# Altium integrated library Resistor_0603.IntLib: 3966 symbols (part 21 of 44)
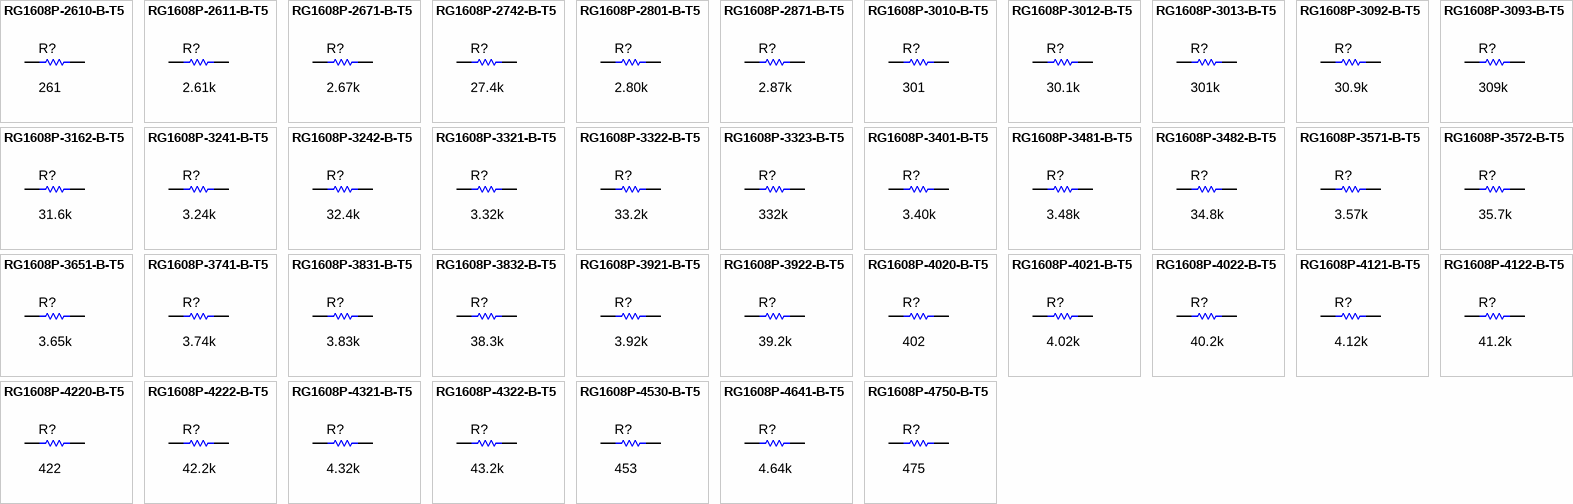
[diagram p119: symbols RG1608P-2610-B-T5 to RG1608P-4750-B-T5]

## RG1608P-2871-B-T5
designator R?  ValueDisplayed: 2.87k  (hidden comment: RG1608P-2871-B-T5)
RES, 2.87 k, 0.1%, 0.1 W, 0603; Manufacturer: Susumu Co Ltd; CompType: Resistor; Value: 2.87k; Res_ohm: 2870; Value_Code: 2k87; Tolerance_%: 0.1; Value2: 0.1W; VDC_V: 75; TempCo: 25 ppm/C; SizeArea_mm2: 1.28; SizeX_mm: 1.6; SizeY_mm: 0.8; SizeZ_mm: 1; EIA_Code: E192; U/M: EA; AEC Category: Q200; Green_Lifecycle: Active; Green_REACh: Passed
signal-integrity model Resistor
simulation model Resistor
footprint 0603
footprint 0603M
footprint 0603L
footprint 0603_HV
footprint 0603S
pins: 1, 2

## RG1608P-3010-B-T5
designator R?  ValueDisplayed: 301  (hidden comment: RG1608P-3010-B-T5)
RES, 301, 0.1%, 0.1 W, 0603; Manufacturer: Susumu Co Ltd; CompType: Resistor; Value: 301; Value_Code: 301R; Tolerance_%: 0.1; Value2: 0.1W; VDC_V: 75; TempCo: 25 ppm/C; SizeArea_mm2: 1.28; SizeX_mm: 1.6; SizeY_mm: 0.8; SizeZ_mm: 1; EIA_Code: E192; U/M: EA; AEC Category: Q200
signal-integrity model Resistor
simulation model Resistor
footprint 0603
footprint 0603M
footprint 0603L
footprint 0603_HV
footprint 0603S
pins: 1, 2

## RG1608P-3012-B-T5
designator R?  ValueDisplayed: 30.1k  (hidden comment: RG1608P-3012-B-T5)
RES, 30.1 k, 0.1%, 0.1 W, 0603; Manufacturer: Susumu Co Ltd; CompType: Resistor; Value: 30.1k; Res_ohm: 30100; Value_Code: 30k1; Tolerance_%: 0.1; Value2: 0.1W; VDC_V: 75; TempCo: 25 ppm/C; SizeArea_mm2: 1.28; SizeX_mm: 1.6; SizeY_mm: 0.8; SizeZ_mm: 1; EIA_Code: E192; U/M: EA; AEC Category: Q200; Green_Lifecycle: Active; Green_REACh: Passed
signal-integrity model Resistor
simulation model Resistor
footprint 0603
footprint 0603M
footprint 0603L
footprint 0603_HV
footprint 0603S
pins: 1, 2

## RG1608P-3013-B-T5
designator R?  ValueDisplayed: 301k  (hidden comment: RG1608P-3013-B-T5)
RES, 301 k, 0.1%, 0.1 W, 0603; Manufacturer: Susumu Co Ltd; CompType: Resistor; Value: 301k; Res_ohm: 301000; Tolerance_%: 0.1; Value2: 0.1W; VDC_V: 75; TempCo: 25 ppm/C; SizeArea_mm2: 1.28; SizeX_mm: 1.6; SizeY_mm: 0.8; SizeZ_mm: 1; EIA_Code: E192; U/M: EA; AEC Category: Q200
signal-integrity model Resistor
simulation model Resistor
footprint 0603
footprint 0603M
footprint 0603L
footprint 0603_HV
footprint 0603S
pins: 1, 2

## RG1608P-3092-B-T5
designator R?  ValueDisplayed: 30.9k  (hidden comment: RG1608P-3092-B-T5)
RES, 30.9 k, 0.1%, 0.1 W, 0603; Manufacturer: Susumu Co Ltd; CompType: Resistor; Value: 30.9k; Res_ohm: 30900; Value_Code: 30k9; Tolerance_%: 0.1; Value2: 0.1W; VDC_V: 75; TempCo: 25 ppm/C; SizeArea_mm2: 1.28; SizeX_mm: 1.6; SizeY_mm: 0.8; SizeZ_mm: 1; EIA_Code: E192; U/M: EA; AEC Category: Q200
signal-integrity model Resistor
simulation model Resistor
footprint 0603
footprint 0603M
footprint 0603L
footprint 0603_HV
footprint 0603S
pins: 1, 2

## RG1608P-3093-B-T5
designator R?  ValueDisplayed: 309k  (hidden comment: RG1608P-3093-B-T5)
RES, 309 k, 0.1%, 0.1 W, 0603; Manufacturer: Susumu Co Ltd; CompType: Resistor; Value: 309k; Res_ohm: 309000; Tolerance_%: 0.1; Value2: 0.1W; VDC_V: 75; TempCo: 25 ppm/C; SizeArea_mm2: 1.28; SizeX_mm: 1.6; SizeY_mm: 0.8; SizeZ_mm: 1; EIA_Code: E192; U/M: EA; AEC Category: Q200
signal-integrity model Resistor
simulation model Resistor
footprint 0603
footprint 0603M
footprint 0603L
footprint 0603_HV
footprint 0603S
pins: 1, 2

## RG1608P-3162-B-T5
designator R?  ValueDisplayed: 31.6k  (hidden comment: RG1608P-3162-B-T5)
RES, 31.6 k, 0.1%, 0.1 W, 0603; Manufacturer: Susumu Co Ltd; CompType: Resistor; Value: 31.6k; Res_ohm: 31600; Value_Code: 31k6; Tolerance_%: 0.1; Value2: 0.1W; VDC_V: 75; TempCo: 25 ppm/C; SizeArea_mm2: 1.28; SizeX_mm: 1.6; SizeY_mm: 0.8; SizeZ_mm: 1; EIA_Code: E192; U/M: EA; AEC Category: Q200
signal-integrity model Resistor
simulation model Resistor
footprint 0603
footprint 0603M
footprint 0603L
footprint 0603_HV
footprint 0603S
pins: 1, 2

## RG1608P-3241-B-T5
designator R?  ValueDisplayed: 3.24k  (hidden comment: RG1608P-3241-B-T5)
RES, 3.24 k, 0.1%, 0.1 W, 0603; Manufacturer: Susumu Co Ltd; CompType: Resistor; Value: 3.24k; Res_ohm: 3240; Value_Code: 3k24; Tolerance_%: 0.1; Value2: 0.1W; VDC_V: 75; TempCo: 25 ppm/C; SizeArea_mm2: 1.28; SizeX_mm: 1.6; SizeY_mm: 0.8; SizeZ_mm: 1; EIA_Code: E192; U/M: EA; AEC Category: Q200
signal-integrity model Resistor
simulation model Resistor
footprint 0603
footprint 0603M
footprint 0603L
footprint 0603_HV
footprint 0603S
pins: 1, 2

## RG1608P-3242-B-T5
designator R?  ValueDisplayed: 32.4k  (hidden comment: RG1608P-3242-B-T5)
RES, 32.4 k, 0.1%, 0.1 W, 0603; Manufacturer: Susumu Co Ltd; CompType: Resistor; Value: 32.4k; Res_ohm: 32400; Value_Code: 32k4; Tolerance_%: 0.1; Value2: 0.1W; VDC_V: 75; TempCo: 25 ppm/C; SizeArea_mm2: 1.28; SizeX_mm: 1.6; SizeY_mm: 0.8; SizeZ_mm: 1; EIA_Code: E192; U/M: EA; AEC Category: Q200; Green_Lifecycle: Active; Green_REACh: Passed
signal-integrity model Resistor
simulation model Resistor
footprint 0603
footprint 0603M
footprint 0603L
footprint 0603_HV
footprint 0603S
pins: 1, 2

## RG1608P-3321-B-T5
designator R?  ValueDisplayed: 3.32k  (hidden comment: RG1608P-3321-B-T5)
RES, 3.32 k, 0.1%, 0.1 W, 0603; Manufacturer: Susumu Co Ltd; CompType: Resistor; Value: 3.32k; Res_ohm: 3320; Value_Code: 3k32; Tolerance_%: 0.1; Value2: 0.1W; VDC_V: 75; TempCo: 25 ppm/C; SizeArea_mm2: 1.28; SizeX_mm: 1.6; SizeY_mm: 0.8; SizeZ_mm: 1; EIA_Code: E192; U/M: EA; AEC Category: Q200
signal-integrity model Resistor
simulation model Resistor
footprint 0603
footprint 0603M
footprint 0603L
footprint 0603_HV
footprint 0603S
pins: 1, 2

## RG1608P-3322-B-T5
designator R?  ValueDisplayed: 33.2k  (hidden comment: RG1608P-3322-B-T5)
RES, 33.2 k, 0.1%, 0.1 W, 0603; Manufacturer: Susumu Co Ltd; CompType: Resistor; Value: 33.2k; Res_ohm: 33200; Value_Code: 33k2; Tolerance_%: 0.1; Value2: 0.1W; VDC_V: 75; TempCo: 25 ppm/C; SizeArea_mm2: 1.28; SizeX_mm: 1.6; SizeY_mm: 0.8; SizeZ_mm: 1; EIA_Code: E192; U/M: EA; AEC Category: Q200
signal-integrity model Resistor
simulation model Resistor
footprint 0603
footprint 0603M
footprint 0603L
footprint 0603_HV
footprint 0603S
pins: 1, 2

## RG1608P-3323-B-T5
designator R?  ValueDisplayed: 332k  (hidden comment: RG1608P-3323-B-T5)
RES, 332 k, 0.1%, 0.1 W, 0603; Manufacturer: Susumu Co Ltd; CompType: Resistor; Value: 332k; Res_ohm: 332000; Tolerance_%: 0.1; Value2: 0.1W; VDC_V: 75; TempCo: 25 ppm/C; SizeArea_mm2: 1.28; SizeX_mm: 1.6; SizeY_mm: 0.8; SizeZ_mm: 1; EIA_Code: E192; U/M: EA; AEC Category: Q200
signal-integrity model Resistor
simulation model Resistor
footprint 0603
footprint 0603M
footprint 0603L
footprint 0603_HV
footprint 0603S
pins: 1, 2

## RG1608P-3401-B-T5
designator R?  ValueDisplayed: 3.40k  (hidden comment: RG1608P-3401-B-T5)
RES, 3.40 k, 0.1%, 0.1 W, 0603; Manufacturer: Susumu Co Ltd; CompType: Resistor; Value: 3.40k; Res_ohm: 3400; Value_Code: 3k40; Tolerance_%: 0.1; Value2: 0.1W; VDC_V: 75; TempCo: 25 ppm/C; SizeArea_mm2: 1.28; SizeX_mm: 1.6; SizeY_mm: 0.8; SizeZ_mm: 1; EIA_Code: E192; U/M: EA; AEC Category: Q200
signal-integrity model Resistor
simulation model Resistor
footprint 0603
footprint 0603M
footprint 0603L
footprint 0603_HV
footprint 0603S
pins: 1, 2

## RG1608P-3481-B-T5
designator R?  ValueDisplayed: 3.48k  (hidden comment: RG1608P-3481-B-T5)
RES, 3.48 k, 0.1%, 0.1 W, 0603; Manufacturer: Susumu Co Ltd; CompType: Resistor; Value: 3.48k; Res_ohm: 3480; Value_Code: 3k48; Tolerance_%: 0.1; Value2: 0.1W; VDC_V: 75; TempCo: 25 ppm/C; SizeArea_mm2: 1.28; SizeX_mm: 1.6; SizeY_mm: 0.8; SizeZ_mm: 1; EIA_Code: E192; U/M: EA; AEC Category: Q200
signal-integrity model Resistor
simulation model Resistor
footprint 0603
footprint 0603M
footprint 0603L
footprint 0603_HV
footprint 0603S
pins: 1, 2

## RG1608P-3482-B-T5
designator R?  ValueDisplayed: 34.8k  (hidden comment: RG1608P-3482-B-T5)
RES, 34.8 k, 0.1%, 0.1 W, 0603; Manufacturer: Susumu Co Ltd; CompType: Resistor; Value: 34.8k; Res_ohm: 34800; Value_Code: 34k8; Tolerance_%: 0.1; Value2: 0.1W; VDC_V: 75; TempCo: 25 ppm/C; SizeArea_mm2: 1.28; SizeX_mm: 1.6; SizeY_mm: 0.8; SizeZ_mm: 1; EIA_Code: E192; U/M: EA; AEC Category: Q200
signal-integrity model Resistor
simulation model Resistor
footprint 0603
footprint 0603M
footprint 0603L
footprint 0603_HV
footprint 0603S
pins: 1, 2

## RG1608P-3571-B-T5
designator R?  ValueDisplayed: 3.57k  (hidden comment: RG1608P-3571-B-T5)
RES, 3.57 k, 0.1%, 0.1 W, 0603; Manufacturer: Susumu Co Ltd; CompType: Resistor; Value: 3.57k; Res_ohm: 3570; Value_Code: 3k57; Tolerance_%: 0.1; Value2: 0.1W; VDC_V: 75; TempCo: 25 ppm/C; SizeArea_mm2: 1.28; SizeX_mm: 1.6; SizeY_mm: 0.8; SizeZ_mm: 1; EIA_Code: E192; U/M: EA; AEC Category: Q200; Green_Lifecycle: Active; Green_REACh: Passed
signal-integrity model Resistor
simulation model Resistor
footprint 0603
footprint 0603M
footprint 0603L
footprint 0603_HV
footprint 0603S
pins: 1, 2

## RG1608P-3572-B-T5
designator R?  ValueDisplayed: 35.7k  (hidden comment: RG1608P-3572-B-T5)
RES, 35.7 k, 0.1%, 0.1 W, 0603; Manufacturer: Susumu Co Ltd; CompType: Resistor; Value: 35.7k; Res_ohm: 35700; Value_Code: 35k7; Tolerance_%: 0.1; Value2: 0.1W; VDC_V: 75; TempCo: 25 ppm/C; SizeArea_mm2: 1.28; SizeX_mm: 1.6; SizeY_mm: 0.8; SizeZ_mm: 1; EIA_Code: E192; U/M: EA; AEC Category: Q200
signal-integrity model Resistor
simulation model Resistor
footprint 0603
footprint 0603M
footprint 0603L
footprint 0603_HV
footprint 0603S
pins: 1, 2

## RG1608P-3651-B-T5
designator R?  ValueDisplayed: 3.65k  (hidden comment: RG1608P-3651-B-T5)
RES, 3.65 k, 0.1%, 0.1 W, 0603; Manufacturer: Susumu Co Ltd; CompType: Resistor; Value: 3.65k; Res_ohm: 3650; Value_Code: 3k65; Tolerance_%: 0.1; Value2: 0.1W; VDC_V: 75; TempCo: 25 ppm/C; SizeArea_mm2: 1.28; SizeX_mm: 1.6; SizeY_mm: 0.8; SizeZ_mm: 1; EIA_Code: E192; U/M: EA; AEC Category: Q200
signal-integrity model Resistor
simulation model Resistor
footprint 0603
footprint 0603M
footprint 0603L
footprint 0603_HV
footprint 0603S
pins: 1, 2

## RG1608P-3741-B-T5
designator R?  ValueDisplayed: 3.74k  (hidden comment: RG1608P-3741-B-T5)
RES, 3.74 k, 0.1%, 0.1 W, 0603; Manufacturer: Susumu Co Ltd; CompType: Resistor; Value: 3.74k; Res_ohm: 3740; Value_Code: 3k74; Tolerance_%: 0.1; Value2: 0.1W; VDC_V: 75; TempCo: 25 ppm/C; SizeArea_mm2: 1.28; SizeX_mm: 1.6; SizeY_mm: 0.8; SizeZ_mm: 1; EIA_Code: E192; U/M: EA; AEC Category: Q200
signal-integrity model Resistor
simulation model Resistor
footprint 0603
footprint 0603M
footprint 0603L
footprint 0603_HV
footprint 0603S
pins: 1, 2

## RG1608P-3831-B-T5
designator R?  ValueDisplayed: 3.83k  (hidden comment: RG1608P-3831-B-T5)
RES, 3.83 k, 0.1%, 0.1 W, 0603; Manufacturer: Susumu Co Ltd; CompType: Resistor; Value: 3.83k; Res_ohm: 3830; Value_Code: 3k83; Tolerance_%: 0.1; Value2: 0.1W; VDC_V: 75; TempCo: 25 ppm/C; SizeArea_mm2: 1.28; SizeX_mm: 1.6; SizeY_mm: 0.8; SizeZ_mm: 1; EIA_Code: E192; U/M: EA; AEC Category: Q200; Green_Lifecycle: Active; Green_REACh: Passed
signal-integrity model Resistor
simulation model Resistor
footprint 0603
footprint 0603M
footprint 0603L
footprint 0603_HV
footprint 0603S
pins: 1, 2

## RG1608P-3832-B-T5
designator R?  ValueDisplayed: 38.3k  (hidden comment: RG1608P-3832-B-T5)
RES, 38.3 k, 0.1%, 0.1 W, 0603; Manufacturer: Susumu Co Ltd; CompType: Resistor; Value: 38.3k; Res_ohm: 38300; Value_Code: 38k3; Tolerance_%: 0.1; Value2: 0.1W; VDC_V: 75; TempCo: 25 ppm/C; SizeArea_mm2: 1.28; SizeX_mm: 1.6; SizeY_mm: 0.8; SizeZ_mm: 1; EIA_Code: E192; U/M: EA; AEC Category: Q200
signal-integrity model Resistor
simulation model Resistor
footprint 0603
footprint 0603M
footprint 0603L
footprint 0603_HV
footprint 0603S
pins: 1, 2

## RG1608P-3921-B-T5
designator R?  ValueDisplayed: 3.92k  (hidden comment: RG1608P-3921-B-T5)
RES, 3.92 k, 0.1%, 0.1 W, 0603; Manufacturer: Susumu Co Ltd; CompType: Resistor; Value: 3.92k; Res_ohm: 3920; Value_Code: 3k92; Tolerance_%: 0.1; Value2: 0.1W; VDC_V: 75; TempCo: 25 ppm/C; SizeArea_mm2: 1.28; SizeX_mm: 1.6; SizeY_mm: 0.8; SizeZ_mm: 1; EIA_Code: E192; U/M: EA; AEC Category: Q200
signal-integrity model Resistor
simulation model Resistor
footprint 0603
footprint 0603M
footprint 0603L
footprint 0603_HV
footprint 0603S
pins: 1, 2

## RG1608P-3922-B-T5
designator R?  ValueDisplayed: 39.2k  (hidden comment: RG1608P-3922-B-T5)
RES, 39.2 k, 0.1%, 0.1 W, 0603; Manufacturer: Susumu Co Ltd; CompType: Resistor; Value: 39.2k; Res_ohm: 39200; Value_Code: 39k2; Tolerance_%: 0.1; Value2: 0.1W; VDC_V: 75; TempCo: 25 ppm/C; SizeArea_mm2: 1.28; SizeX_mm: 1.6; SizeY_mm: 0.8; SizeZ_mm: 1; EIA_Code: E192; U/M: EA; AEC Category: Q200; Green_Lifecycle: Active; Green_REACh: Passed
signal-integrity model Resistor
simulation model Resistor
footprint 0603
footprint 0603M
footprint 0603L
footprint 0603_HV
footprint 0603S
pins: 1, 2

## RG1608P-4020-B-T5
designator R?  ValueDisplayed: 402  (hidden comment: RG1608P-4020-B-T5)
RES, 402, 0.1%, 0.1 W, 0603; Manufacturer: Susumu Co Ltd; CompType: Resistor; Value: 402; Value_Code: 402R; Tolerance_%: 0.1; Value2: 0.1W; VDC_V: 75; TempCo: 25 ppm/C; SizeArea_mm2: 1.28; SizeX_mm: 1.6; SizeY_mm: 0.8; SizeZ_mm: 1; EIA_Code: E192; U/M: EA; AEC Category: Q200
signal-integrity model Resistor
simulation model Resistor
footprint 0603
footprint 0603M
footprint 0603L
footprint 0603_HV
footprint 0603S
pins: 1, 2

## RG1608P-4021-B-T5
designator R?  ValueDisplayed: 4.02k  (hidden comment: RG1608P-4021-B-T5)
RES, 4.02 k, 0.1%, 0.1 W, 0603; Manufacturer: Susumu Co Ltd; CompType: Resistor; Value: 4.02k; Res_ohm: 4020; Value_Code: 4k02; Tolerance_%: 0.1; Value2: 0.1W; VDC_V: 75; TempCo: 25 ppm/C; SizeArea_mm2: 1.28; SizeX_mm: 1.6; SizeY_mm: 0.8; SizeZ_mm: 1; EIA_Code: E192; U/M: EA; AEC Category: Q200
signal-integrity model Resistor
simulation model Resistor
footprint 0603
footprint 0603M
footprint 0603L
footprint 0603_HV
footprint 0603S
pins: 1, 2

## RG1608P-4022-B-T5
designator R?  ValueDisplayed: 40.2k  (hidden comment: RG1608P-4022-B-T5)
RES, 40.2 k, 0.1%, 0.1 W, 0603; Manufacturer: Susumu Co Ltd; CompType: Resistor; Value: 40.2k; Res_ohm: 40200; Value_Code: 40k2; Tolerance_%: 0.1; Value2: 0.1W; VDC_V: 75; TempCo: 25 ppm/C; SizeArea_mm2: 1.28; SizeX_mm: 1.6; SizeY_mm: 0.8; SizeZ_mm: 1; EIA_Code: E192; U/M: EA; AEC Category: Q200
signal-integrity model Resistor
simulation model Resistor
footprint 0603
footprint 0603M
footprint 0603L
footprint 0603_HV
footprint 0603S
pins: 1, 2

## RG1608P-4121-B-T5
designator R?  ValueDisplayed: 4.12k  (hidden comment: RG1608P-4121-B-T5)
RES, 4.12 k, 0.1%, 0.1 W, 0603; Manufacturer: Susumu Co Ltd; CompType: Resistor; Value: 4.12k; Res_ohm: 4120; Value_Code: 4k12; Tolerance_%: 0.1; Value2: 0.1W; VDC_V: 75; TempCo: 25 ppm/C; SizeArea_mm2: 1.28; SizeX_mm: 1.6; SizeY_mm: 0.8; SizeZ_mm: 1; EIA_Code: E192; U/M: EA; AEC Category: Q200
signal-integrity model Resistor
simulation model Resistor
footprint 0603
footprint 0603M
footprint 0603L
footprint 0603_HV
footprint 0603S
pins: 1, 2

## RG1608P-4122-B-T5
designator R?  ValueDisplayed: 41.2k  (hidden comment: RG1608P-4122-B-T5)
RES, 41.2 k, 0.1%, 0.1 W, 0603; Manufacturer: Susumu Co Ltd; CompType: Resistor; Value: 41.2k; Res_ohm: 41200; Value_Code: 41k2; Tolerance_%: 0.1; Value2: 0.1W; VDC_V: 75; TempCo: 25 ppm/C; SizeArea_mm2: 1.28; SizeX_mm: 1.6; SizeY_mm: 0.8; SizeZ_mm: 1; EIA_Code: E192; U/M: EA; AEC Category: Q200
signal-integrity model Resistor
simulation model Resistor
footprint 0603
footprint 0603M
footprint 0603L
footprint 0603_HV
footprint 0603S
pins: 1, 2

## RG1608P-4220-B-T5
designator R?  ValueDisplayed: 422  (hidden comment: RG1608P-4220-B-T5)
RES, 422, 0.1%, 0.1 W, 0603; Manufacturer: Susumu Co Ltd; CompType: Resistor; Value: 422; Value_Code: 422R; Tolerance_%: 0.1; Value2: 0.1W; VDC_V: 75; TempCo: 25 ppm/C; SizeArea_mm2: 1.28; SizeX_mm: 1.6; SizeY_mm: 0.8; SizeZ_mm: 1; EIA_Code: E192; U/M: EA; AEC Category: Q200
signal-integrity model Resistor
simulation model Resistor
footprint 0603
footprint 0603M
footprint 0603L
footprint 0603_HV
footprint 0603S
pins: 1, 2

## RG1608P-4222-B-T5
designator R?  ValueDisplayed: 42.2k  (hidden comment: RG1608P-4222-B-T5)
RES, 42.2 k, 0.1%, 0.1 W, 0603; Manufacturer: Susumu Co Ltd; CompType: Resistor; Value: 42.2k; Res_ohm: 42200; Value_Code: 42k2; Tolerance_%: 0.1; Value2: 0.1W; VDC_V: 75; TempCo: 25 ppm/C; SizeArea_mm2: 1.28; SizeX_mm: 1.6; SizeY_mm: 0.8; SizeZ_mm: 1; EIA_Code: E192; U/M: EA; AEC Category: Q200; Green_Lifecycle: Active; Green_REACh: Passed
signal-integrity model Resistor
simulation model Resistor
footprint 0603
footprint 0603M
footprint 0603L
footprint 0603_HV
footprint 0603S
pins: 1, 2

## RG1608P-4321-B-T5
designator R?  ValueDisplayed: 4.32k  (hidden comment: RG1608P-4321-B-T5)
RES, 4.32 k, 0.1%, 0.1 W, 0603; Manufacturer: Susumu Co Ltd; CompType: Resistor; Value: 4.32k; Res_ohm: 4320; Value_Code: 4k32; Tolerance_%: 0.1; Value2: 0.1W; VDC_V: 75; TempCo: 25 ppm/C; SizeArea_mm2: 1.28; SizeX_mm: 1.6; SizeY_mm: 0.8; SizeZ_mm: 1; EIA_Code: E192; U/M: EA; AEC Category: Q200
signal-integrity model Resistor
simulation model Resistor
footprint 0603
footprint 0603M
footprint 0603L
footprint 0603_HV
footprint 0603S
pins: 1, 2

## RG1608P-4322-B-T5
designator R?  ValueDisplayed: 43.2k  (hidden comment: RG1608P-4322-B-T5)
RES, 43.2 k, 0.1%, 0.1 W, 0603; Manufacturer: Susumu Co Ltd; CompType: Resistor; Value: 43.2k; Res_ohm: 43200; Value_Code: 43k2; Tolerance_%: 0.1; Value2: 0.1W; VDC_V: 75; TempCo: 25 ppm/C; SizeArea_mm2: 1.28; SizeX_mm: 1.6; SizeY_mm: 0.8; SizeZ_mm: 1; EIA_Code: E192; U/M: EA; AEC Category: Q200
signal-integrity model Resistor
simulation model Resistor
footprint 0603
footprint 0603M
footprint 0603L
footprint 0603_HV
footprint 0603S
pins: 1, 2

## RG1608P-4530-B-T5
designator R?  ValueDisplayed: 453  (hidden comment: RG1608P-4530-B-T5)
RES, 453, 0.1%, 0.1 W, 0603; Manufacturer: Susumu Co Ltd; CompType: Resistor; Value: 453; Value_Code: 453R; Tolerance_%: 0.1; Value2: 0.1W; VDC_V: 75; TempCo: 25 ppm/C; SizeArea_mm2: 1.28; SizeX_mm: 1.6; SizeY_mm: 0.8; SizeZ_mm: 1; EIA_Code: E192; U/M: EA; AEC Category: Q200
signal-integrity model Resistor
simulation model Resistor
footprint 0603
footprint 0603M
footprint 0603L
footprint 0603_HV
footprint 0603S
pins: 1, 2

## RG1608P-4641-B-T5
designator R?  ValueDisplayed: 4.64k  (hidden comment: RG1608P-4641-B-T5)
RES, 4.64 k, 0.1%, 0.1 W, 0603; Manufacturer: Susumu Co Ltd; CompType: Resistor; Value: 4.64k; Res_ohm: 4640; Value_Code: 4k64; Tolerance_%: 0.1; Value2: 0.1W; VDC_V: 75; TempCo: 25 ppm/C; SizeArea_mm2: 1.28; SizeX_mm: 1.6; SizeY_mm: 0.8; SizeZ_mm: 1; EIA_Code: E192; U/M: EA; AEC Category: Q200
signal-integrity model Resistor
simulation model Resistor
footprint 0603
footprint 0603M
footprint 0603L
footprint 0603_HV
footprint 0603S
pins: 1, 2

## RG1608P-4750-B-T5
designator R?  ValueDisplayed: 475  (hidden comment: RG1608P-4750-B-T5)
RES, 475, 0.1%, 0.1 W, 0603; Manufacturer: Susumu Co Ltd; CompType: Resistor; Value: 475; Value_Code: 475R; Tolerance_%: 0.1; Value2: 0.1W; VDC_V: 75; TempCo: 25 ppm/C; SizeArea_mm2: 1.28; SizeX_mm: 1.6; SizeY_mm: 0.8; SizeZ_mm: 1; EIA_Code: E192; U/M: EA; AEC Category: Q200
signal-integrity model Resistor
simulation model Resistor
footprint 0603
footprint 0603M
footprint 0603L
footprint 0603_HV
footprint 0603S
pins: 1, 2

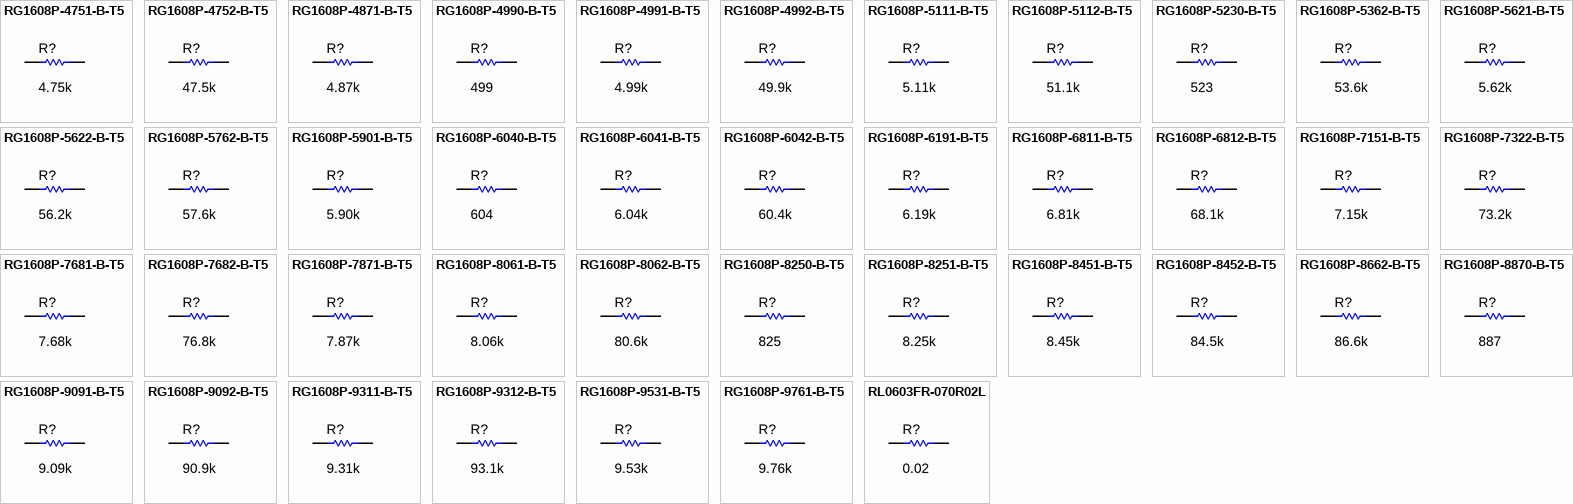
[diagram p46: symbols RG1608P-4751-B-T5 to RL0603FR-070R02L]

## RG1608P-4751-B-T5
designator R?  ValueDisplayed: 4.75k  (hidden comment: RG1608P-4751-B-T5)
RES, 4.75 k, 0.1%, 0.1 W, 0603; Manufacturer: Susumu Co Ltd; CompType: Resistor; Value: 4.75k; Res_ohm: 4750; Value_Code: 4k75; Tolerance_%: 0.1; Value2: 0.1W; VDC_V: 75; TempCo: 25 ppm/C; SizeArea_mm2: 1.28; SizeX_mm: 1.6; SizeY_mm: 0.8; SizeZ_mm: 1; EIA_Code: E192; U/M: EA; AEC Category: Q200
signal-integrity model Resistor
simulation model Resistor
footprint 0603
footprint 0603M
footprint 0603L
footprint 0603_HV
footprint 0603S
pins: 1, 2

## RG1608P-4752-B-T5
designator R?  ValueDisplayed: 47.5k  (hidden comment: RG1608P-4752-B-T5)
RES, 47.5 k, 0.1%, 0.1 W, 0603; Manufacturer: Susumu Co Ltd; CompType: Resistor; Value: 47.5k; Res_ohm: 47500; Value_Code: 47k5; Tolerance_%: 0.1; Value2: 0.1W; VDC_V: 75; TempCo: 25 ppm/C; SizeArea_mm2: 1.28; SizeX_mm: 1.6; SizeY_mm: 0.8; SizeZ_mm: 1; EIA_Code: E192; U/M: EA; AEC Category: Q200
signal-integrity model Resistor
simulation model Resistor
footprint 0603
footprint 0603M
footprint 0603L
footprint 0603_HV
footprint 0603S
pins: 1, 2

## RG1608P-4871-B-T5
designator R?  ValueDisplayed: 4.87k  (hidden comment: RG1608P-4871-B-T5)
RES, 4.87 k, 0.1%, 0.1 W, 0603; Manufacturer: Susumu Co Ltd; CompType: Resistor; Value: 4.87k; Res_ohm: 4870; Value_Code: 4k87; Tolerance_%: 0.1; Value2: 0.1W; VDC_V: 75; TempCo: 25 ppm/C; SizeArea_mm2: 1.28; SizeX_mm: 1.6; SizeY_mm: 0.8; SizeZ_mm: 1; EIA_Code: E192; U/M: EA; AEC Category: Q200; Green_Lifecycle: Active; Green_REACh: Passed
signal-integrity model Resistor
simulation model Resistor
footprint 0603
footprint 0603M
footprint 0603L
footprint 0603_HV
footprint 0603S
pins: 1, 2

## RG1608P-4990-B-T5
designator R?  ValueDisplayed: 499  (hidden comment: RG1608P-4990-B-T5)
RES, 499, 0.1%, 0.1 W, 0603; Manufacturer: Susumu Co Ltd; CompType: Resistor; Value: 499; Value_Code: 499R; Tolerance_%: 0.1; Value2: 0.1W; VDC_V: 75; TempCo: 25 ppm/C; SizeArea_mm2: 1.28; SizeX_mm: 1.6; SizeY_mm: 0.8; SizeZ_mm: 1; EIA_Code: E192; U/M: EA; AEC Category: Q200; Green_Lifecycle: Active; Green_REACh: Passed
signal-integrity model Resistor
simulation model Resistor
footprint 0603
footprint 0603M
footprint 0603L
footprint 0603_HV
footprint 0603S
pins: 1, 2

## RG1608P-4991-B-T5
designator R?  ValueDisplayed: 4.99k  (hidden comment: RG1608P-4991-B-T5)
RES, 4.99 k, 0.1%, 0.1 W, 0603; Manufacturer: Susumu Co Ltd; CompType: Resistor; Value: 4.99k; Res_ohm: 4990; Value_Code: 4k99; Tolerance_%: 0.1; Value2: 0.1W; VDC_V: 75; TempCo: 25 ppm/C; SizeArea_mm2: 1.28; SizeX_mm: 1.6; SizeY_mm: 0.8; SizeZ_mm: 1; EIA_Code: E192; U/M: EA; AEC Category: Q200; Green_Lifecycle: Active; Green_REACh: Passed
signal-integrity model Resistor
simulation model Resistor
footprint 0603
footprint 0603M
footprint 0603L
footprint 0603_HV
footprint 0603S
pins: 1, 2

## RG1608P-4992-B-T5
designator R?  ValueDisplayed: 49.9k  (hidden comment: RG1608P-4992-B-T5)
RES, 49.9 k, 0.1%, 0.1 W, 0603; Manufacturer: Susumu Co Ltd; CompType: Resistor; Value: 49.9k; Res_ohm: 49900; Value_Code: 49k9; Tolerance_%: 0.1; Value2: 0.1W; VDC_V: 75; TempCo: 25 ppm/C; SizeArea_mm2: 1.28; SizeX_mm: 1.6; SizeY_mm: 0.8; SizeZ_mm: 1; EIA_Code: E192; U/M: EA; AEC Category: Q200; Green_Lifecycle: Active; Green_REACh: Passed
signal-integrity model Resistor
simulation model Resistor
footprint 0603
footprint 0603M
footprint 0603L
footprint 0603_HV
footprint 0603S
pins: 1, 2

## RG1608P-5111-B-T5
designator R?  ValueDisplayed: 5.11k  (hidden comment: RG1608P-5111-B-T5)
RES, 5.11 k, 0.1%, 0.1 W, 0603; Manufacturer: Susumu Co Ltd; CompType: Resistor; Value: 5.11k; Res_ohm: 5110; Value_Code: 5k11; Tolerance_%: 0.1; Value2: 0.1W; VDC_V: 75; TempCo: 25 ppm/C; SizeArea_mm2: 1.28; SizeX_mm: 1.6; SizeY_mm: 0.8; SizeZ_mm: 1; EIA_Code: E192; U/M: EA; AEC Category: Q200
signal-integrity model Resistor
simulation model Resistor
footprint 0603
footprint 0603M
footprint 0603L
footprint 0603_HV
footprint 0603S
pins: 1, 2

## RG1608P-5112-B-T5
designator R?  ValueDisplayed: 51.1k  (hidden comment: RG1608P-5112-B-T5)
RES, 51.1 k, 0.1%, 0.1 W, 0603; Manufacturer: Susumu Co Ltd; CompType: Resistor; Value: 51.1k; Res_ohm: 51100; Value_Code: 51k1; Tolerance_%: 0.1; Value2: 0.1W; VDC_V: 75; TempCo: 25 ppm/C; SizeArea_mm2: 1.28; SizeX_mm: 1.6; SizeY_mm: 0.8; SizeZ_mm: 1; EIA_Code: E192; U/M: EA; AEC Category: Q200
signal-integrity model Resistor
simulation model Resistor
footprint 0603
footprint 0603M
footprint 0603L
footprint 0603_HV
footprint 0603S
pins: 1, 2

## RG1608P-5230-B-T5
designator R?  ValueDisplayed: 523  (hidden comment: RG1608P-5230-B-T5)
RES, 523, 0.1%, 0.1 W, 0603; Manufacturer: Susumu Co Ltd; CompType: Resistor; Value: 523; Value_Code: 523R; Tolerance_%: 0.1; Value2: 0.1W; VDC_V: 75; TempCo: 25 ppm/C; SizeArea_mm2: 1.28; SizeX_mm: 1.6; SizeY_mm: 0.8; SizeZ_mm: 1; EIA_Code: E192; U/M: EA; AEC Category: Q200
signal-integrity model Resistor
simulation model Resistor
footprint 0603
footprint 0603M
footprint 0603L
footprint 0603_HV
footprint 0603S
pins: 1, 2

## RG1608P-5362-B-T5
designator R?  ValueDisplayed: 53.6k  (hidden comment: RG1608P-5362-B-T5)
RES, 53.6 k, 0.1%, 0.1 W, 0603; Manufacturer: Susumu Co Ltd; CompType: Resistor; Value: 53.6k; Res_ohm: 53600; Value_Code: 53k6; Tolerance_%: 0.1; Value2: 0.1W; VDC_V: 75; TempCo: 25 ppm/C; SizeArea_mm2: 1.28; SizeX_mm: 1.6; SizeY_mm: 0.8; SizeZ_mm: 1; EIA_Code: E192; U/M: EA; AEC Category: Q200
signal-integrity model Resistor
simulation model Resistor
footprint 0603
footprint 0603M
footprint 0603L
footprint 0603_HV
footprint 0603S
pins: 1, 2

## RG1608P-5621-B-T5
designator R?  ValueDisplayed: 5.62k  (hidden comment: RG1608P-5621-B-T5)
RES, 5.62 k, 0.1%, 0.1 W, 0603; Manufacturer: Susumu Co Ltd; CompType: Resistor; Value: 5.62k; Res_ohm: 5620; Value_Code: 5k62; Tolerance_%: 0.1; Value2: 0.1W; VDC_V: 75; TempCo: 25 ppm/C; SizeArea_mm2: 1.28; SizeX_mm: 1.6; SizeY_mm: 0.8; SizeZ_mm: 1; EIA_Code: E192; U/M: EA; AEC Category: Q200
signal-integrity model Resistor
simulation model Resistor
footprint 0603
footprint 0603M
footprint 0603L
footprint 0603_HV
footprint 0603S
pins: 1, 2

## RG1608P-5622-B-T5
designator R?  ValueDisplayed: 56.2k  (hidden comment: RG1608P-5622-B-T5)
RES, 56.2 k, 0.1%, 0.1 W, 0603; Manufacturer: Susumu Co Ltd; CompType: Resistor; Value: 56.2k; Res_ohm: 56200; Value_Code: 56k2; Tolerance_%: 0.1; Value2: 0.1W; VDC_V: 75; TempCo: 25 ppm/C; SizeArea_mm2: 1.28; SizeX_mm: 1.6; SizeY_mm: 0.8; SizeZ_mm: 1; EIA_Code: E192; U/M: EA; AEC Category: Q200
signal-integrity model Resistor
simulation model Resistor
footprint 0603
footprint 0603M
footprint 0603L
footprint 0603_HV
footprint 0603S
pins: 1, 2

## RG1608P-5762-B-T5
designator R?  ValueDisplayed: 57.6k  (hidden comment: RG1608P-5762-B-T5)
RES, 57.6 k, 0.1%, 0.1 W, 0603; Manufacturer: Susumu Co Ltd; CompType: Resistor; Value: 57.6k; Res_ohm: 57600; Value_Code: 57k6; Tolerance_%: 0.1; Value2: 0.1W; VDC_V: 75; TempCo: 25 ppm/C; SizeArea_mm2: 1.28; SizeX_mm: 1.6; SizeY_mm: 0.8; SizeZ_mm: 1; EIA_Code: E192; U/M: EA; AEC Category: Q200
signal-integrity model Resistor
simulation model Resistor
footprint 0603
footprint 0603M
footprint 0603L
footprint 0603_HV
footprint 0603S
pins: 1, 2

## RG1608P-5901-B-T5
designator R?  ValueDisplayed: 5.90k  (hidden comment: RG1608P-5901-B-T5)
RES, 5.90 k, 0.1%, 0.1 W, 0603; Manufacturer: Susumu Co Ltd; CompType: Resistor; Value: 5.90k; Res_ohm: 5900; Value_Code: 5k90; Tolerance_%: 0.1; Value2: 0.1W; VDC_V: 75; TempCo: 25 ppm/C; SizeArea_mm2: 1.28; SizeX_mm: 1.6; SizeY_mm: 0.8; SizeZ_mm: 1; EIA_Code: E192; U/M: EA; AEC Category: Q200
signal-integrity model Resistor
simulation model Resistor
footprint 0603
footprint 0603M
footprint 0603L
footprint 0603_HV
footprint 0603S
pins: 1, 2

## RG1608P-6040-B-T5
designator R?  ValueDisplayed: 604  (hidden comment: RG1608P-6040-B-T5)
RES, 604, 0.1%, 0.1 W, 0603; Manufacturer: Susumu Co Ltd; CompType: Resistor; Value: 604; Value_Code: 604R; Tolerance_%: 0.1; Value2: 0.1W; VDC_V: 75; TempCo: 25 ppm/C; SizeArea_mm2: 1.28; SizeX_mm: 1.6; SizeY_mm: 0.8; SizeZ_mm: 1; EIA_Code: E192; U/M: EA; AEC Category: Q200
signal-integrity model Resistor
simulation model Resistor
footprint 0603
footprint 0603M
footprint 0603L
footprint 0603_HV
footprint 0603S
pins: 1, 2

## RG1608P-6041-B-T5
designator R?  ValueDisplayed: 6.04k  (hidden comment: RG1608P-6041-B-T5)
RES, 6.04 k, 0.1%, 0.1 W, 0603; Manufacturer: Susumu Co Ltd; CompType: Resistor; Value: 6.04k; Res_ohm: 6040; Value_Code: 6k04; Tolerance_%: 0.1; Value2: 0.1W; VDC_V: 75; TempCo: 25 ppm/C; SizeArea_mm2: 1.28; SizeX_mm: 1.6; SizeY_mm: 0.8; SizeZ_mm: 1; EIA_Code: E192; U/M: EA; AEC Category: Q200; Green_Lifecycle: Active; Green_REACh: Passed
signal-integrity model Resistor
simulation model Resistor
footprint 0603
footprint 0603M
footprint 0603L
footprint 0603_HV
footprint 0603S
pins: 1, 2

## RG1608P-6042-B-T5
designator R?  ValueDisplayed: 60.4k  (hidden comment: RG1608P-6042-B-T5)
RES, 60.4 k, 0.1%, 0.1 W, 0603; Manufacturer: Susumu Co Ltd; CompType: Resistor; Value: 60.4k; Res_ohm: 60400; Value_Code: 60k4; Tolerance_%: 0.1; Value2: 0.1W; VDC_V: 75; TempCo: 25 ppm/C; SizeArea_mm2: 1.28; SizeX_mm: 1.6; SizeY_mm: 0.8; SizeZ_mm: 1; EIA_Code: E192; U/M: EA; AEC Category: Q200
signal-integrity model Resistor
simulation model Resistor
footprint 0603
footprint 0603M
footprint 0603L
footprint 0603_HV
footprint 0603S
pins: 1, 2

## RG1608P-6191-B-T5
designator R?  ValueDisplayed: 6.19k  (hidden comment: RG1608P-6191-B-T5)
RES, 6.19 k, 0.1%, 0.1 W, 0603; Manufacturer: Susumu Co Ltd; CompType: Resistor; Value: 6.19k; Res_ohm: 6190; Value_Code: 6k19; Tolerance_%: 0.1; Value2: 0.1W; VDC_V: 75; TempCo: 25 ppm/C; SizeArea_mm2: 1.28; SizeX_mm: 1.6; SizeY_mm: 0.8; SizeZ_mm: 1; EIA_Code: E192; U/M: EA; AEC Category: Q200
signal-integrity model Resistor
simulation model Resistor
footprint 0603
footprint 0603M
footprint 0603L
footprint 0603_HV
footprint 0603S
pins: 1, 2

## RG1608P-6811-B-T5
designator R?  ValueDisplayed: 6.81k  (hidden comment: RG1608P-6811-B-T5)
RES, 6.81 k, 0.1%, 0.1 W, 0603; Manufacturer: Susumu Co Ltd; CompType: Resistor; Value: 6.81k; Res_ohm: 6810; Value_Code: 6k81; Tolerance_%: 0.1; Value2: 0.1W; VDC_V: 75; TempCo: 25 ppm/C; SizeArea_mm2: 1.28; SizeX_mm: 1.6; SizeY_mm: 0.8; SizeZ_mm: 1; EIA_Code: E192; U/M: EA; AEC Category: Q200
signal-integrity model Resistor
simulation model Resistor
footprint 0603
footprint 0603M
footprint 0603L
footprint 0603_HV
footprint 0603S
pins: 1, 2

## RG1608P-6812-B-T5
designator R?  ValueDisplayed: 68.1k  (hidden comment: RG1608P-6812-B-T5)
RES, 68.1 k, 0.1%, 0.1 W, 0603; Manufacturer: Susumu Co Ltd; CompType: Resistor; Value: 68.1k; Res_ohm: 68100; Value_Code: 68k1; Tolerance_%: 0.1; Value2: 0.1W; VDC_V: 75; TempCo: 25 ppm/C; SizeArea_mm2: 1.28; SizeX_mm: 1.6; SizeY_mm: 0.8; SizeZ_mm: 1; EIA_Code: E192; U/M: EA; AEC Category: Q200
signal-integrity model Resistor
simulation model Resistor
footprint 0603
footprint 0603M
footprint 0603L
footprint 0603_HV
footprint 0603S
pins: 1, 2

## RG1608P-7151-B-T5
designator R?  ValueDisplayed: 7.15k  (hidden comment: RG1608P-7151-B-T5)
RES, 7.15 k, 0.1%, 0.1 W, 0603; Manufacturer: Susumu Co Ltd; CompType: Resistor; Value: 7.15k; Res_ohm: 7150; Value_Code: 7k15; Tolerance_%: 0.1; Value2: 0.1W; VDC_V: 75; TempCo: 25 ppm/C; SizeArea_mm2: 1.28; SizeX_mm: 1.6; SizeY_mm: 0.8; SizeZ_mm: 1; EIA_Code: E192; U/M: EA; AEC Category: Q200
signal-integrity model Resistor
simulation model Resistor
footprint 0603
footprint 0603M
footprint 0603L
footprint 0603_HV
footprint 0603S
pins: 1, 2

## RG1608P-7322-B-T5
designator R?  ValueDisplayed: 73.2k  (hidden comment: RG1608P-7322-B-T5)
RES, 73.2 k, 0.1%, 0.1 W, 0603; Manufacturer: Susumu Co Ltd; CompType: Resistor; Value: 73.2k; Res_ohm: 73200; Value_Code: 73k2; Tolerance_%: 0.1; Value2: 0.1W; VDC_V: 75; TempCo: 25 ppm/C; SizeArea_mm2: 1.28; SizeX_mm: 1.6; SizeY_mm: 0.8; SizeZ_mm: 1; EIA_Code: E192; U/M: EA; AEC Category: Q200
signal-integrity model Resistor
simulation model Resistor
footprint 0603
footprint 0603M
footprint 0603L
footprint 0603_HV
footprint 0603S
pins: 1, 2

## RG1608P-7681-B-T5
designator R?  ValueDisplayed: 7.68k  (hidden comment: RG1608P-7681-B-T5)
RES, 7.68 k, 0.1%, 0.1 W, 0603; Manufacturer: Susumu Co Ltd; CompType: Resistor; Value: 7.68k; Res_ohm: 7680; Value_Code: 7k68; Tolerance_%: 0.1; Value2: 0.1W; VDC_V: 75; TempCo: 25 ppm/C; SizeArea_mm2: 1.28; SizeX_mm: 1.6; SizeY_mm: 0.8; SizeZ_mm: 1; EIA_Code: E192; U/M: EA; AEC Category: Q200; Green_Lifecycle: Active; Green_REACh: Passed
signal-integrity model Resistor
simulation model Resistor
footprint 0603
footprint 0603M
footprint 0603L
footprint 0603_HV
footprint 0603S
pins: 1, 2

## RG1608P-7682-B-T5
designator R?  ValueDisplayed: 76.8k  (hidden comment: RG1608P-7682-B-T5)
RES, 76.8 k, 0.1%, 0.1 W, 0603; Manufacturer: Susumu Co Ltd; CompType: Resistor; Value: 76.8k; Res_ohm: 76800; Value_Code: 76k8; Tolerance_%: 0.1; Value2: 0.1W; VDC_V: 75; TempCo: 25 ppm/C; SizeArea_mm2: 1.28; SizeX_mm: 1.6; SizeY_mm: 0.8; SizeZ_mm: 1; EIA_Code: E192; U/M: EA; AEC Category: Q200
signal-integrity model Resistor
simulation model Resistor
footprint 0603
footprint 0603M
footprint 0603L
footprint 0603_HV
footprint 0603S
pins: 1, 2

## RG1608P-7871-B-T5
designator R?  ValueDisplayed: 7.87k  (hidden comment: RG1608P-7871-B-T5)
RES, 7.87 k, 0.1%, 0.1 W, 0603; Manufacturer: Susumu Co Ltd; CompType: Resistor; Value: 7.87k; Res_ohm: 7870; Value_Code: 7k87; Tolerance_%: 0.1; Value2: 0.1W; VDC_V: 75; TempCo: 25 ppm/C; SizeArea_mm2: 1.28; SizeX_mm: 1.6; SizeY_mm: 0.8; SizeZ_mm: 1; EIA_Code: E192; U/M: EA; AEC Category: Q200
signal-integrity model Resistor
simulation model Resistor
footprint 0603
footprint 0603M
footprint 0603L
footprint 0603_HV
footprint 0603S
pins: 1, 2

## RG1608P-8061-B-T5
designator R?  ValueDisplayed: 8.06k  (hidden comment: RG1608P-8061-B-T5)
RES, 8.06 k, 0.1%, 0.1 W, 0603; Manufacturer: Susumu Co Ltd; CompType: Resistor; Value: 8.06k; Res_ohm: 8060; Value_Code: 8k06; Tolerance_%: 0.1; Value2: 0.1W; VDC_V: 75; TempCo: 25 ppm/C; SizeArea_mm2: 1.28; SizeX_mm: 1.6; SizeY_mm: 0.8; SizeZ_mm: 1; EIA_Code: E192; U/M: EA; AEC Category: Q200
signal-integrity model Resistor
simulation model Resistor
footprint 0603
footprint 0603M
footprint 0603L
footprint 0603_HV
footprint 0603S
pins: 1, 2

## RG1608P-8062-B-T5
designator R?  ValueDisplayed: 80.6k  (hidden comment: RG1608P-8062-B-T5)
RES, 80.6 k, 0.1%, 0.1 W, 0603; Manufacturer: Susumu Co Ltd; CompType: Resistor; Value: 80.6k; Res_ohm: 80600; Value_Code: 80k6; Tolerance_%: 0.1; Value2: 0.1W; VDC_V: 75; TempCo: 25 ppm/C; SizeArea_mm2: 1.28; SizeX_mm: 1.6; SizeY_mm: 0.8; SizeZ_mm: 1; EIA_Code: E192; U/M: EA; AEC Category: Q200
signal-integrity model Resistor
simulation model Resistor
footprint 0603
footprint 0603M
footprint 0603L
footprint 0603_HV
footprint 0603S
pins: 1, 2

## RG1608P-8250-B-T5
designator R?  ValueDisplayed: 825  (hidden comment: RG1608P-8250-B-T5)
RES, 825, 0.1%, 0.1 W, 0603; Manufacturer: Susumu Co Ltd; CompType: Resistor; Value: 825; Value_Code: 825R; Tolerance_%: 0.1; Value2: 0.1W; VDC_V: 75; TempCo: 25 ppm/C; SizeArea_mm2: 1.28; SizeX_mm: 1.6; SizeY_mm: 0.8; SizeZ_mm: 1; EIA_Code: E192; U/M: EA; AEC Category: Q200
signal-integrity model Resistor
simulation model Resistor
footprint 0603
footprint 0603M
footprint 0603L
footprint 0603_HV
footprint 0603S
pins: 1, 2

## RG1608P-8251-B-T5
designator R?  ValueDisplayed: 8.25k  (hidden comment: RG1608P-8251-B-T5)
RES, 8.25 k, 0.1%, 0.1 W, 0603; Manufacturer: Susumu Co Ltd; CompType: Resistor; Value: 8.25k; Res_ohm: 8250; Value_Code: 8k25; Tolerance_%: 0.1; Value2: 0.1W; VDC_V: 75; TempCo: 25 ppm/C; SizeArea_mm2: 1.28; SizeX_mm: 1.6; SizeY_mm: 0.8; SizeZ_mm: 1; EIA_Code: E192; U/M: EA; AEC Category: Q200
signal-integrity model Resistor
simulation model Resistor
footprint 0603
footprint 0603M
footprint 0603L
footprint 0603_HV
footprint 0603S
pins: 1, 2

## RG1608P-8451-B-T5
designator R?  ValueDisplayed: 8.45k  (hidden comment: RG1608P-8451-B-T5)
RES, 8.45 k, 0.1%, 0.1 W, 0603; Manufacturer: Susumu Co Ltd; CompType: Resistor; Value: 8.45k; Res_ohm: 8450; Value_Code: 8k45; Tolerance_%: 0.1; Value2: 0.1W; VDC_V: 75; TempCo: 25 ppm/C; SizeArea_mm2: 1.28; SizeX_mm: 1.6; SizeY_mm: 0.8; SizeZ_mm: 1; EIA_Code: E192; U/M: EA; AEC Category: Q200
signal-integrity model Resistor
simulation model Resistor
footprint 0603
footprint 0603M
footprint 0603L
footprint 0603_HV
footprint 0603S
pins: 1, 2

## RG1608P-8452-B-T5
designator R?  ValueDisplayed: 84.5k  (hidden comment: RG1608P-8452-B-T5)
RES, 84.5 k, 0.1%, 0.1 W, 0603; Manufacturer: Susumu Co Ltd; CompType: Resistor; Value: 84.5k; Res_ohm: 84500; Value_Code: 84k5; Tolerance_%: 0.1; Value2: 0.1W; VDC_V: 75; TempCo: 25 ppm/C; SizeArea_mm2: 1.28; SizeX_mm: 1.6; SizeY_mm: 0.8; SizeZ_mm: 1; EIA_Code: E192; U/M: EA; AEC Category: Q200
signal-integrity model Resistor
simulation model Resistor
footprint 0603
footprint 0603M
footprint 0603L
footprint 0603_HV
footprint 0603S
pins: 1, 2

## RG1608P-8662-B-T5
designator R?  ValueDisplayed: 86.6k  (hidden comment: RG1608P-8662-B-T5)
RES, 86.6 k, 0.1%, 0.1 W, 0603; Manufacturer: Susumu Co Ltd; CompType: Resistor; Value: 86.6k; Res_ohm: 86600; Value_Code: 86k6; Tolerance_%: 0.1; Value2: 0.1W; VDC_V: 75; TempCo: 25 ppm/C; SizeArea_mm2: 1.28; SizeX_mm: 1.6; SizeY_mm: 0.8; SizeZ_mm: 1; EIA_Code: E192; U/M: EA; AEC Category: Q200
signal-integrity model Resistor
simulation model Resistor
footprint 0603
footprint 0603M
footprint 0603L
footprint 0603_HV
footprint 0603S
pins: 1, 2

## RG1608P-8870-B-T5
designator R?  ValueDisplayed: 887  (hidden comment: RG1608P-8870-B-T5)
RES, 887, 0.1%, 0.1 W, 0603; Manufacturer: Susumu Co Ltd; CompType: Resistor; Value: 887; Value_Code: 887R; Tolerance_%: 0.1; Value2: 0.1W; VDC_V: 75; TempCo: 25 ppm/C; SizeArea_mm2: 1.28; SizeX_mm: 1.6; SizeY_mm: 0.8; SizeZ_mm: 1; EIA_Code: E192; U/M: EA; AEC Category: Q200
signal-integrity model Resistor
simulation model Resistor
footprint 0603
footprint 0603M
footprint 0603L
footprint 0603_HV
footprint 0603S
pins: 1, 2

## RG1608P-9091-B-T5
designator R?  ValueDisplayed: 9.09k  (hidden comment: RG1608P-9091-B-T5)
RES, 9.09 k, 0.1%, 0.1 W, 0603; Manufacturer: Susumu Co Ltd; CompType: Resistor; Value: 9.09k; Res_ohm: 9090; Value_Code: 9k09; Tolerance_%: 0.1; Value2: 0.1W; VDC_V: 75; TempCo: 25 ppm/C; SizeArea_mm2: 1.28; SizeX_mm: 1.6; SizeY_mm: 0.8; SizeZ_mm: 1; EIA_Code: E192; U/M: EA; AEC Category: Q200
signal-integrity model Resistor
simulation model Resistor
footprint 0603
footprint 0603M
footprint 0603L
footprint 0603_HV
footprint 0603S
pins: 1, 2

## RG1608P-9092-B-T5
designator R?  ValueDisplayed: 90.9k  (hidden comment: RG1608P-9092-B-T5)
RES, 90.9 k, 0.1%, 0.1 W, 0603; Manufacturer: Susumu Co Ltd; CompType: Resistor; Value: 90.9k; Res_ohm: 90900; Value_Code: 90k9; Tolerance_%: 0.1; Value2: 0.1W; VDC_V: 75; TempCo: 25 ppm/C; SizeArea_mm2: 1.28; SizeX_mm: 1.6; SizeY_mm: 0.8; SizeZ_mm: 1; EIA_Code: E192; U/M: EA; AEC Category: Q200; Green_Lifecycle: Active; Green_REACh: Passed
signal-integrity model Resistor
simulation model Resistor
footprint 0603
footprint 0603M
footprint 0603L
footprint 0603_HV
footprint 0603S
pins: 1, 2

## RG1608P-9311-B-T5
designator R?  ValueDisplayed: 9.31k  (hidden comment: RG1608P-9311-B-T5)
RES, 9.31 k, 0.1%, 0.1 W, 0603; Manufacturer: Susumu Co Ltd; CompType: Resistor; Value: 9.31k; Res_ohm: 9310; Value_Code: 9k31; Tolerance_%: 0.1; Value2: 0.1W; VDC_V: 75; TempCo: 25 ppm/C; SizeArea_mm2: 1.28; SizeX_mm: 1.6; SizeY_mm: 0.8; SizeZ_mm: 1; EIA_Code: E192; U/M: EA; AEC Category: Q200
signal-integrity model Resistor
simulation model Resistor
footprint 0603
footprint 0603M
footprint 0603L
footprint 0603_HV
footprint 0603S
pins: 1, 2

## RG1608P-9312-B-T5
designator R?  ValueDisplayed: 93.1k  (hidden comment: RG1608P-9312-B-T5)
RES, 93.1 k, 0.1%, 0.1 W, 0603; Manufacturer: Susumu Co Ltd; CompType: Resistor; Value: 93.1k; Res_ohm: 93100; Value_Code: 93k1; Tolerance_%: 0.1; Value2: 0.1W; VDC_V: 75; TempCo: 25 ppm/C; SizeArea_mm2: 1.28; SizeX_mm: 1.6; SizeY_mm: 0.8; SizeZ_mm: 1; EIA_Code: E192; U/M: EA; AEC Category: Q200; Green_Lifecycle: Active; Green_REACh: Passed
signal-integrity model Resistor
simulation model Resistor
footprint 0603
footprint 0603M
footprint 0603L
footprint 0603_HV
footprint 0603S
pins: 1, 2

## RG1608P-9531-B-T5
designator R?  ValueDisplayed: 9.53k  (hidden comment: RG1608P-9531-B-T5)
RES, 9.53 k, 0.1%, 0.1 W, 0603; Manufacturer: Susumu Co Ltd; CompType: Resistor; Value: 9.53k; Res_ohm: 9530; Value_Code: 9k53; Tolerance_%: 0.1; Value2: 0.1W; VDC_V: 75; TempCo: 25 ppm/C; SizeArea_mm2: 1.28; SizeX_mm: 1.6; SizeY_mm: 0.8; SizeZ_mm: 1; EIA_Code: E192; U/M: EA; AEC Category: Q200
signal-integrity model Resistor
simulation model Resistor
footprint 0603
footprint 0603M
footprint 0603L
footprint 0603_HV
footprint 0603S
pins: 1, 2

## RG1608P-9761-B-T5
designator R?  ValueDisplayed: 9.76k  (hidden comment: RG1608P-9761-B-T5)
RES, 9.76 k, 0.1%, 0.1 W, 0603; Manufacturer: Susumu Co Ltd; CompType: Resistor; Value: 9.76k; Res_ohm: 9760; Value_Code: 9k76; Tolerance_%: 0.1; Value2: 0.1W; VDC_V: 75; TempCo: 25 ppm/C; SizeArea_mm2: 1.28; SizeX_mm: 1.6; SizeY_mm: 0.8; SizeZ_mm: 1; EIA_Code: E192; U/M: EA; AEC Category: Q200
signal-integrity model Resistor
simulation model Resistor
footprint 0603
footprint 0603M
footprint 0603L
footprint 0603_HV
footprint 0603S
pins: 1, 2

## RL0603FR-070R02L
designator R?  ValueDisplayed: 0.02  (hidden comment: RL0603FR-070R02L)
RES, 0.02, 1%, 0.1 W, AEC-Q200 Grade 0, 0603; Manufacturer: Yageo America; CompType: Resistor; Value: 0.02; Value_Code: R020; Tolerance_%: 1; Power_W: 0.1; Value2: 0.1W; TempCo: 1500 ppm/C; SizeArea_mm2: 1.28; SizeX_mm: 1.6; SizeY_mm: 0.8; EIA_Code: E96; U/M: EA; AEC Category: Q200; AEC Qualified: Y; AEC Grade: 0
signal-integrity model Resistor
simulation model Resistor
footprint 0603
footprint 0603M
footprint 0603L
footprint 0603_HV
footprint 0603S
pins: 1, 2

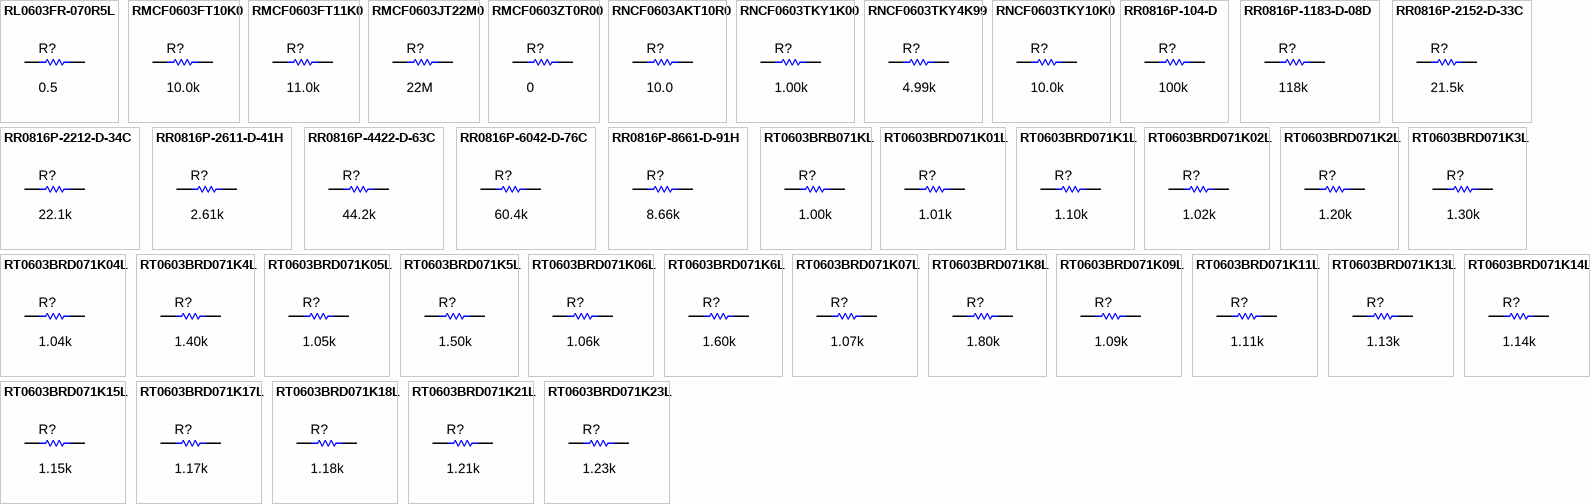
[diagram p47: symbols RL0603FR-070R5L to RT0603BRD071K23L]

## RL0603FR-070R5L
designator R?  ValueDisplayed: 0.5  (hidden comment: RL0603FR-070R5L)
RES, 0.5, 1%, 0.1 W, 0603; Manufacturer: Yageo America; CompType: Resistor; Value: 0.5; Value_Code: R500; Tolerance_%: 1; Power_W: 0.1; Value2: 0.1W; TempCo: 800 ppm/C; SizeArea_mm2: 1.28; SizeX_mm: 1.6; SizeY_mm: 0.8; U/M: EA; AEC Category: Q200; Green_Lifecycle: Active; Green_REACh: Passed
signal-integrity model Resistor
simulation model Resistor
footprint 0603
footprint 0603M
footprint 0603L
footprint 0603_HV
footprint 0603S
pins: 1, 2

## RMCF0603FT10K0
designator R?  ValueDisplayed: 10.0k  (hidden comment: RMCF0603FT10K0)
RES, 10.0 k, 1%, 0.1 W, AEC-Q200 Grade 0, 0603; Manufacturer: Stackpole Electronics Inc; CompType: Resistor; Value: 10.0k; Res_ohm: 10000; Value_Code: 10k0; Tolerance_%: 1; Power_W: 0.1; Value2: 0.1W; VDC_V: 75; TempCo: 100 ppm/C; SizeArea_mm2: 1.28; SizeX_mm: 1.6; SizeY_mm: 0.8; EIA_Code: E96; U/M: EA; AEC Category: Q200; AEC Qualified: Y; AEC Grade: 0
signal-integrity model Resistor
simulation model Resistor
footprint 0603
footprint 0603M
footprint 0603L
footprint 0603_HV
footprint 0603S
pins: 1, 2

## RMCF0603FT11K0
designator R?  ValueDisplayed: 11.0k  (hidden comment: RMCF0603FT11K0)
RES, 11.0 k, 1%, 0.1 W, AEC-Q200 Grade 0, 0603; Manufacturer: Stackpole Electronics Inc; CompType: Resistor; Value: 11.0k; Res_ohm: 11000; Value_Code: 11k0; Tolerance_%: 1; Power_W: 0.1; Value2: 0.1W; VDC_V: 75; TempCo: 100 ppm/C; SizeArea_mm2: 1.28; SizeX_mm: 1.6; SizeY_mm: 0.8; EIA_Code: E96; U/M: EA; AEC Category: Q200; AEC Qualified: Y; AEC Grade: 0; Green_Lifecycle: Active; Green_REACh: Passed
signal-integrity model Resistor
simulation model Resistor
footprint 0603
footprint 0603M
footprint 0603L
footprint 0603_HV
footprint 0603S
pins: 1, 2

## RMCF0603JT22M0
designator R?  ValueDisplayed: 22M  (hidden comment: RMCF0603JT22M0)
RES, 22 M, 5%, 0.1 W, AEC-Q200 Grade 0, 0603; Manufacturer: Stackpole Electronics Inc; CompType: Resistor; Value: 22Meg; Res_ohm: 22000000; Value_Code: 22M0; Tolerance_%: 5; Power_W: 0.1; Value2: 0.1W; VDC_V: 75; TempCo: 200 ppm/C; SizeArea_mm2: 1.28; SizeX_mm: 1.6; SizeY_mm: 0.8; SizeZ_mm: 1; U/M: EA; AEC Category: Q200; AEC Qualified: Y; AEC Grade: 0
signal-integrity model Resistor
simulation model Resistor
footprint 0603
footprint 0603M
footprint 0603L
footprint 0603_HV
footprint 0603S
pins: 1, 2

## RMCF0603ZT0R00
designator R?  ValueDisplayed: 0  (hidden comment: RMCF0603ZT0R00)
RES, 0, 1%, 0.1 W, AEC-Q200 Grade 0, 0603; Manufacturer: Stackpole Electronics Inc; CompType: Resistor; Value: 0; Tolerance_%: 1; Power_W: 0.1; Value2: 0.1W; TempCo: ppm/C; SizeArea_mm2: 1.28; SizeX_mm: 1.6; SizeY_mm: 0.8; U/M: EA; AEC Category: Q200; AEC Qualified: Y; Green_Lifecycle: Active; Green_REACh: Passed
signal-integrity model Resistor
simulation model Resistor
footprint 0603
footprint 0603M
footprint 0603L
footprint 0603_HV
footprint 0603S
pins: 1, 2

## RNCF0603AKT10R0
designator R?  ValueDisplayed: 10.0  (hidden comment: RNCF0603AKT10R0)
RES, 10.0, 0.05%, 0.1 W, 0603; Manufacturer: Stackpole Electronics Inc; CompType: Resistor; Value: 10.0; Res_ohm: 10; Value_Code: 10R0; Tolerance_%: 0.05; Power_W: 0.1; Value2: 0.1W; VDC_V: 50; TempCo: 10 ppm/C; SizeArea_mm2: 1.28; SizeX_mm: 1.6; SizeY_mm: 0.8; SizeZ_mm: 1; U/M: EA; AEC Category: Q200
signal-integrity model Resistor
simulation model Resistor
footprint 0603
footprint 0603M
footprint 0603L
footprint 0603_HV
footprint 0603S
pins: 1, 2

## RNCF0603TKY1K00
designator R?  ValueDisplayed: 1.00k  (hidden comment: RNCF0603TKY1K00)
RES, 1.00 k, 0.01%, 0.063 W, 0603; Manufacturer: Stackpole Electronics Inc; CompType: Resistor; Value: 1.00k; Res_ohm: 1000; Value_Code: 1k00; Tolerance_%: 0.01; Power_W: 0.063; Value2: 0.063W; VDC_V: 50; TempCo: 5 ppm/C; SizeArea_mm2: 1.28; SizeX_mm: 1.6; SizeY_mm: 0.8; SizeZ_mm: 1; U/M: EA; AEC Category: Q200; Green_Lifecycle: Active; Green_REACh: Passed
signal-integrity model Resistor
simulation model Resistor
footprint 0603
footprint 0603M
footprint 0603L
footprint 0603_HV
footprint 0603S
pins: 1, 2

## RNCF0603TKY4K99
designator R?  ValueDisplayed: 4.99k  (hidden comment: RNCF0603TKY4K99)
RES, 4.99 k, 0.01%, 0.1 W, 0603; Manufacturer: Stackpole Electronics Inc; CompType: Resistor; Value: 4.99k; Res_ohm: 4990; Value_Code: 4k99; Tolerance_%: 0.01; Power_W: 0.1; Value2: 0.1W; VDC_V: 75; TempCo: 5 ppm/C; SizeArea_mm2: 1.28; SizeX_mm: 1.6; SizeY_mm: 0.8; SizeZ_mm: 1; EIA_Code: E192; U/M: EA; AEC Category: Q200; AEC Qualified: N
signal-integrity model Resistor
simulation model Resistor
footprint 0603
footprint 0603M
footprint 0603L
footprint 0603_HV
footprint 0603S
pins: 1, 2

## RNCF0603TKY10K0
designator R?  ValueDisplayed: 10.0k  (hidden comment: RNCF0603TKY10K0)
RES, 10.0 k, 0.01%, 0.063 W, 0603; Manufacturer: Stackpole Electronics Inc; CompType: Resistor; Value: 10.0k; Res_ohm: 10000; Value_Code: 10k0; Tolerance_%: 0.01; Power_W: 0.063; Value2: 0.063W; VDC_V: 50; TempCo: 5 ppm/C; SizeArea_mm2: 1.28; SizeX_mm: 1.6; SizeY_mm: 0.8; SizeZ_mm: 1; U/M: EA; AEC Category: Q200
signal-integrity model Resistor
simulation model Resistor
footprint 0603
footprint 0603M
footprint 0603L
footprint 0603_HV
footprint 0603S
pins: 1, 2

## RR0816P-104-D
designator R?  ValueDisplayed: 100k  (hidden comment: RR0816P-104-D)
RES, 100 k, 0.5%, 0.0625 W, 0603; Manufacturer: Susumu Co Ltd; CompType: Resistor; Value: 100k; Res_ohm: 100000; Tolerance_%: 0.5; Power_W: 0.0625; VDC_V: 75; TempCo: 25 ppm/C; SizeArea_mm2: 1.3175; SizeX_mm: 1.55; SizeY_mm: 0.85; EIA_Code: E192; U/M: EA; AEC Category: Q200; AEC Qualified: N; Green_Lifecycle: Active; Green_REACh: Passed
signal-integrity model Resistor
simulation model Resistor
footprint 0603_HR
pins: 1, 2

## RR0816P-1183-D-08D
designator R?  ValueDisplayed: 118k  (hidden comment: RR0816P-1183-D-08D)
RES, 118 k, 0.5%, 0.0625 W, 0603; Manufacturer: Susumu Co Ltd; CompType: Resistor; Value: 118k; Res_ohm: 118000; Tolerance_%: 0.5; Power_W: 0.0625; VDC_V: 75; TempCo: 25 ppm/C; SizeArea_mm2: 1.3175; SizeX_mm: 1.55; SizeY_mm: 0.85; EIA_Code: E192; U/M: EA; AEC Category: Q200; AEC Qualified: N
signal-integrity model Resistor
simulation model Resistor
footprint 0603_HR
pins: 1, 2

## RR0816P-2152-D-33C
designator R?  ValueDisplayed: 21.5k  (hidden comment: RR0816P-2152-D-33C)
RES, 21.5 k, 0.5%, 0.0625 W, 0603; Manufacturer: Susumu Co Ltd; CompType: Resistor; Value: 21.5k; Res_ohm: 21500; Value_Code: 21k5; Tolerance_%: 0.5; Power_W: 0.0625; VDC_V: 75; TempCo: 25 ppm/C; SizeArea_mm2: 1.3175; SizeX_mm: 1.55; SizeY_mm: 0.85; EIA_Code: E192; U/M: EA; AEC Category: Q200; AEC Qualified: N; Green_Lifecycle: Active; Green_REACh: Passed
signal-integrity model Resistor
simulation model Resistor
footprint 0603_HR
pins: 1, 2

## RR0816P-2212-D-34C
designator R?  ValueDisplayed: 22.1k  (hidden comment: RR0816P-2212-D-34C)
RES, 22.1 k, 0.5%, 0.0625 W, 0603; Manufacturer: Susumu Co Ltd; CompType: Resistor; Value: 22.1k; Res_ohm: 22100; Value_Code: 22k1; Tolerance_%: 0.5; Power_W: 0.0625; VDC_V: 75; TempCo: 25 ppm/C; SizeArea_mm2: 1.3175; SizeX_mm: 1.55; SizeY_mm: 0.85; EIA_Code: E192; U/M: EA; AEC Category: Q200; AEC Qualified: N
signal-integrity model Resistor
simulation model Resistor
footprint 0603_HR
pins: 1, 2

## RR0816P-2611-D-41H
designator R?  ValueDisplayed: 2.61k  (hidden comment: RR0816P-2611-D-41H)
RES, 2.61 k, 0.5%, 0.0625 W, 0603; Manufacturer: Susumu Co Ltd; CompType: Resistor; Value: 2.61k; Res_ohm: 2610; Value_Code: 2k61; Tolerance_%: 0.5; Power_W: 0.0625; VDC_V: 75; TempCo: 25 ppm/C; SizeArea_mm2: 1.3175; SizeX_mm: 1.55; SizeY_mm: 0.85; EIA_Code: E192; U/M: EA; AEC Category: Q200; AEC Qualified: N
signal-integrity model Resistor
simulation model Resistor
footprint 0603_HR
pins: 1, 2

## RR0816P-4422-D-63C
designator R?  ValueDisplayed: 44.2k  (hidden comment: RR0816P-4422-D-63C)
RES, 44.2 k, 0.5%, 0.0625 W, 0603; Manufacturer: Susumu Co Ltd; CompType: Resistor; Value: 44.2k; Res_ohm: 44200; Value_Code: 44k2; Tolerance_%: 0.5; Power_W: 0.0625; VDC_V: 75; TempCo: 25 ppm/C; SizeArea_mm2: 1.3175; SizeX_mm: 1.55; SizeY_mm: 0.85; EIA_Code: E192; U/M: EA; AEC Category: Q200; AEC Qualified: N; Green_Lifecycle: Active; Green_REACh: Passed
signal-integrity model Resistor
simulation model Resistor
footprint 0603_HR
pins: 1, 2

## RR0816P-6042-D-76C
designator R?  ValueDisplayed: 60.4k  (hidden comment: RR0816P-6042-D-76C)
RES, 60.4 k, 0.5%, 0.0625 W, 0603; Manufacturer: Susumu Co Ltd; CompType: Resistor; Value: 60.4k; Res_ohm: 60400; Value_Code: 60k4; Tolerance_%: 0.5; Power_W: 0.0625; VDC_V: 75; TempCo: 25 ppm/C; SizeArea_mm2: 1.3175; SizeX_mm: 1.55; SizeY_mm: 0.85; EIA_Code: E192; U/M: EA; AEC Category: Q200; AEC Qualified: N
signal-integrity model Resistor
simulation model Resistor
footprint 0603_HR
pins: 1, 2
